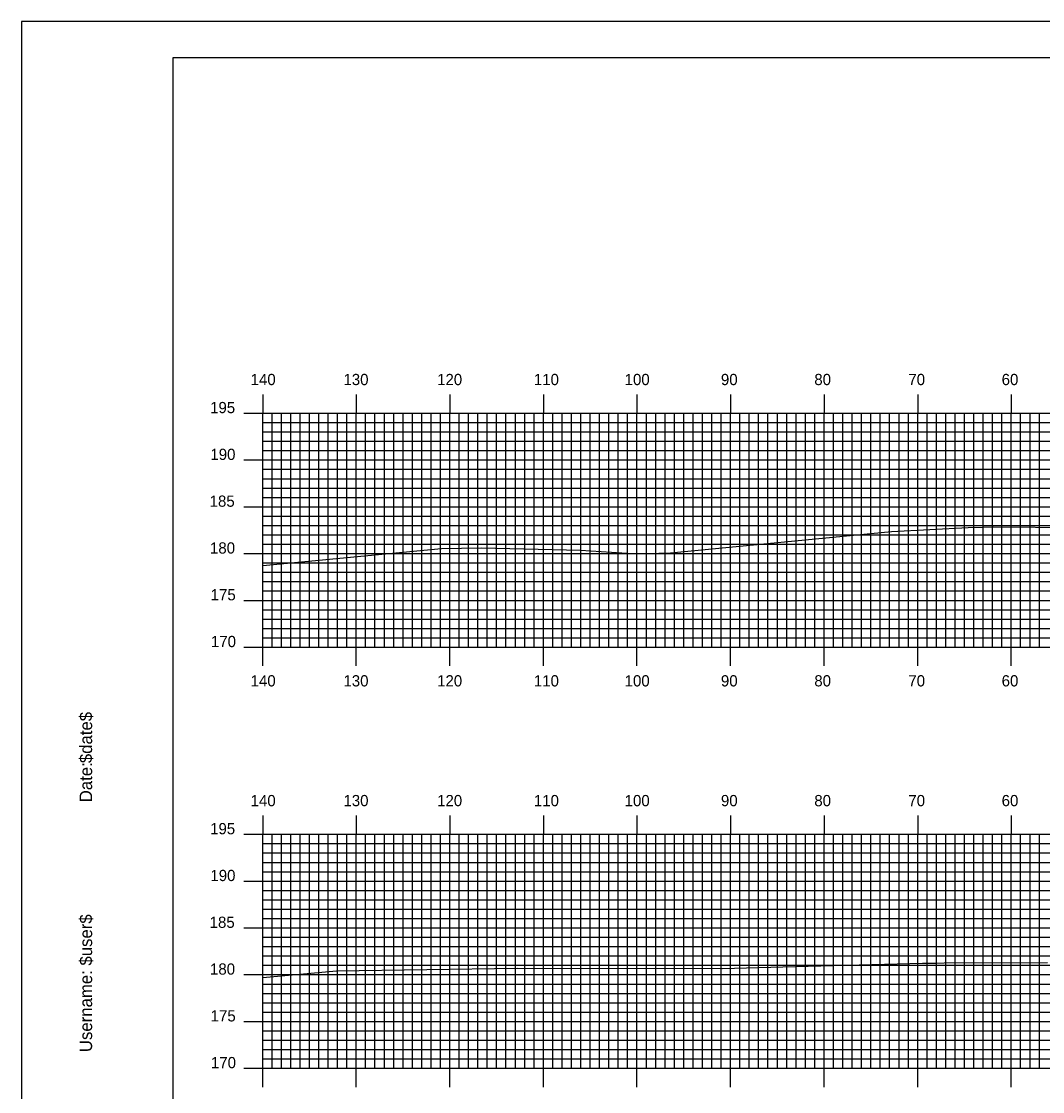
# Model space of a CAD drawing. Extents: x 1823571 to 1823914, y 442310 to 442530.
# Drawn here: x 1823571.1 to 1823680.2, y 442415.6 to 442530 of the extents above; entities that cross this region are included whole.
import ezdxf

# ---------------------------------------------------------------- set-up
doc = ezdxf.new("R2010")
doc.units = 0
for name, color, linetype in [('BORDER', 7, 'Continuous'), ('H_V ANNOTATION', 7, 'Continuous'), ('MAJOR', 7, 'Continuous'), ('MINOR', 7, 'Continuous'), ('PLOT BOUNDARY', 7, 'Continuous'), ('S_Roadway_Centerline', 7, 'Continuous')]:
    doc.layers.add(name, color=color, linetype=linetype)

msp = doc.modelspace()

# ---------------------------------------------------------------- linework, layer by layer
at = {"layer": 'BORDER'}
msp.add_lwpolyline([(1823587.3, 442316.11), (1823907.3, 442316.11), (1823907.3, 442526.11), (1823587.3, 442526.11)], close=True, dxfattribs=at)
at = {"layer": 'MAJOR'}
for p, q in [((1823596.9, 442490.12), (1823596.9, 442488.12)), ((1823606.9, 442490.12), (1823606.9, 442488.12)), ((1823616.9, 442490.12), (1823616.9, 442488.12)), ((1823626.9, 442490.12), (1823626.9, 442488.12)), ((1823636.9, 442490.12), (1823636.9, 442488.12)), ((1823646.9, 442490.12), (1823646.9, 442488.12)), ((1823656.9, 442490.12), (1823656.9, 442488.12)), ((1823666.9, 442490.12), (1823666.9, 442488.12)), ((1823676.9, 442490.12), (1823676.9, 442488.12)), ((1823594.9, 442488.12), (1823596.9, 442488.12)), ((1823596.9, 442488.12), (1823876.9, 442488.12)), ((1823596.9, 442463.12), (1823596.9, 442488.12)), ((1823596.9, 442463.12), (1823596.9, 442488.12)), ((1823596.9, 442488.12), (1823876.9, 442488.12)), ((1823606.9, 442463.12), (1823606.9, 442488.12)), ((1823616.9, 442463.12), (1823616.9, 442488.12)), ((1823626.9, 442463.12), (1823626.9, 442488.12)), ((1823636.9, 442463.12), (1823636.9, 442488.12)), ((1823646.9, 442463.12), (1823646.9, 442488.12)), ((1823656.9, 442463.12), (1823656.9, 442488.12)), ((1823666.9, 442463.12), (1823666.9, 442488.12)), ((1823676.9, 442463.12), (1823676.9, 442488.12)), ((1823594.9, 442483.12), (1823596.9, 442483.12)), ((1823596.9, 442483.12), (1823876.9, 442483.12)), ((1823594.9, 442478.12), (1823596.9, 442478.12)), ((1823596.9, 442478.12), (1823876.9, 442478.12)), ((1823594.9, 442473.12), (1823596.9, 442473.12)), ((1823596.9, 442473.12), (1823876.9, 442473.12)), ((1823594.9, 442468.12), (1823596.9, 442468.12)), ((1823596.9, 442468.12), (1823876.9, 442468.12)), ((1823594.9, 442463.12), (1823596.9, 442463.12)), ((1823596.9, 442463.12), (1823876.9, 442463.12)), ((1823596.9, 442463.12), (1823876.9, 442463.12)), ((1823596.9, 442461.11), (1823596.9, 442463.12)), ((1823606.9, 442461.11), (1823606.9, 442463.12)), ((1823616.9, 442461.11), (1823616.9, 442463.12)), ((1823626.9, 442461.11), (1823626.9, 442463.12)), ((1823636.9, 442461.11), (1823636.9, 442463.12)), ((1823646.9, 442461.11), (1823646.9, 442463.12)), ((1823656.9, 442461.11), (1823656.9, 442463.12)), ((1823666.9, 442461.11), (1823666.9, 442463.12)), ((1823676.9, 442461.11), (1823676.9, 442463.12)), ((1823596.9, 442445.12), (1823596.9, 442443.12)), ((1823606.9, 442445.12), (1823606.9, 442443.12)), ((1823616.9, 442445.12), (1823616.9, 442443.12)), ((1823626.9, 442445.12), (1823626.9, 442443.12)), ((1823636.9, 442445.12), (1823636.9, 442443.12)), ((1823646.9, 442445.12), (1823646.9, 442443.12)), ((1823656.9, 442445.12), (1823656.9, 442443.12)), ((1823666.9, 442445.12), (1823666.9, 442443.12)), ((1823676.9, 442445.12), (1823676.9, 442443.12)), ((1823594.9, 442443.12), (1823596.9, 442443.12)), ((1823596.9, 442443.12), (1823876.9, 442443.12)), ((1823596.9, 442418.12), (1823596.9, 442443.12)), ((1823596.9, 442418.12), (1823596.9, 442443.12)), ((1823596.9, 442443.12), (1823876.9, 442443.12)), ((1823606.9, 442418.12), (1823606.9, 442443.12)), ((1823616.9, 442418.12), (1823616.9, 442443.12)), ((1823626.9, 442418.12), (1823626.9, 442443.12)), ((1823636.9, 442418.12), (1823636.9, 442443.12)), ((1823646.9, 442418.12), (1823646.9, 442443.12)), ((1823656.9, 442418.12), (1823656.9, 442443.12)), ((1823666.9, 442418.12), (1823666.9, 442443.12)), ((1823676.9, 442418.12), (1823676.9, 442443.12)), ((1823594.9, 442438.12), (1823596.9, 442438.12)), ((1823596.9, 442438.12), (1823876.9, 442438.12)), ((1823594.9, 442433.12), (1823596.9, 442433.12)), ((1823596.9, 442433.12), (1823876.9, 442433.12)), ((1823594.9, 442428.12), (1823596.9, 442428.12)), ((1823596.9, 442428.12), (1823876.9, 442428.12)), ((1823594.9, 442423.12), (1823596.9, 442423.12)), ((1823596.9, 442423.12), (1823876.9, 442423.12)), ((1823594.9, 442418.12), (1823596.9, 442418.12)), ((1823596.9, 442418.12), (1823876.9, 442418.12)), ((1823596.9, 442418.12), (1823876.9, 442418.12)), ((1823596.9, 442416.11), (1823596.9, 442418.12)), ((1823606.9, 442416.11), (1823606.9, 442418.12)), ((1823616.9, 442416.11), (1823616.9, 442418.12)), ((1823626.9, 442416.11), (1823626.9, 442418.12)), ((1823636.9, 442416.11), (1823636.9, 442418.12)), ((1823646.9, 442416.11), (1823646.9, 442418.12)), ((1823656.9, 442416.11), (1823656.9, 442418.12)), ((1823666.9, 442416.11), (1823666.9, 442418.12)), ((1823676.9, 442416.11), (1823676.9, 442418.12))]:
    msp.add_line(p, q, dxfattribs=at)
at = {"layer": 'MINOR'}
for p, q in [((1823597.9, 442463.12), (1823597.9, 442488.12)), ((1823598.9, 442463.12), (1823598.9, 442488.12)), ((1823599.9, 442463.12), (1823599.9, 442488.12)), ((1823600.9, 442463.12), (1823600.9, 442488.12)), ((1823601.9, 442463.12), (1823601.9, 442488.12)), ((1823602.9, 442463.12), (1823602.9, 442488.12)), ((1823603.9, 442463.12), (1823603.9, 442488.12)), ((1823604.9, 442463.12), (1823604.9, 442488.12)), ((1823605.9, 442463.12), (1823605.9, 442488.12)), ((1823607.9, 442463.12), (1823607.9, 442488.12)), ((1823608.9, 442463.12), (1823608.9, 442488.12)), ((1823609.9, 442463.12), (1823609.9, 442488.12)), ((1823610.9, 442463.12), (1823610.9, 442488.12)), ((1823611.9, 442463.12), (1823611.9, 442488.12)), ((1823612.9, 442463.12), (1823612.9, 442488.12)), ((1823613.9, 442463.12), (1823613.9, 442488.12)), ((1823614.9, 442463.12), (1823614.9, 442488.12)), ((1823615.9, 442463.12), (1823615.9, 442488.12)), ((1823617.9, 442463.12), (1823617.9, 442488.12)), ((1823618.9, 442463.12), (1823618.9, 442488.12)), ((1823619.9, 442463.12), (1823619.9, 442488.12)), ((1823620.9, 442463.12), (1823620.9, 442488.12)), ((1823621.9, 442463.12), (1823621.9, 442488.12)), ((1823622.9, 442463.12), (1823622.9, 442488.12)), ((1823623.9, 442463.12), (1823623.9, 442488.12)), ((1823624.9, 442463.12), (1823624.9, 442488.12)), ((1823625.9, 442463.12), (1823625.9, 442488.12)), ((1823627.9, 442463.12), (1823627.9, 442488.12)), ((1823628.9, 442463.12), (1823628.9, 442488.12)), ((1823629.9, 442463.12), (1823629.9, 442488.12)), ((1823630.9, 442463.12), (1823630.9, 442488.12)), ((1823631.9, 442463.12), (1823631.9, 442488.12)), ((1823632.9, 442463.12), (1823632.9, 442488.12)), ((1823633.9, 442463.12), (1823633.9, 442488.12)), ((1823634.9, 442463.12), (1823634.9, 442488.12)), ((1823635.9, 442463.12), (1823635.9, 442488.12)), ((1823637.9, 442463.12), (1823637.9, 442488.12)), ((1823638.9, 442463.12), (1823638.9, 442488.12)), ((1823639.9, 442463.12), (1823639.9, 442488.12)), ((1823640.9, 442463.12), (1823640.9, 442488.12)), ((1823641.9, 442463.12), (1823641.9, 442488.12)), ((1823642.9, 442463.12), (1823642.9, 442488.12)), ((1823643.9, 442463.12), (1823643.9, 442488.12)), ((1823644.9, 442463.12), (1823644.9, 442488.12)), ((1823645.9, 442463.12), (1823645.9, 442488.12)), ((1823647.9, 442463.12), (1823647.9, 442488.12)), ((1823648.9, 442463.12), (1823648.9, 442488.12)), ((1823649.9, 442463.12), (1823649.9, 442488.12)), ((1823650.9, 442463.12), (1823650.9, 442488.12)), ((1823651.9, 442463.12), (1823651.9, 442488.12)), ((1823652.9, 442463.12), (1823652.9, 442488.12)), ((1823653.9, 442463.12), (1823653.9, 442488.12)), ((1823654.9, 442463.12), (1823654.9, 442488.12)), ((1823655.9, 442463.12), (1823655.9, 442488.12)), ((1823657.9, 442463.12), (1823657.9, 442488.12)), ((1823658.9, 442463.12), (1823658.9, 442488.12)), ((1823659.9, 442463.12), (1823659.9, 442488.12)), ((1823660.9, 442463.12), (1823660.9, 442488.12)), ((1823661.9, 442463.12), (1823661.9, 442488.12)), ((1823662.9, 442463.12), (1823662.9, 442488.12)), ((1823663.9, 442463.12), (1823663.9, 442488.12)), ((1823664.9, 442463.12), (1823664.9, 442488.12)), ((1823665.9, 442463.12), (1823665.9, 442488.12)), ((1823667.9, 442463.12), (1823667.9, 442488.12)), ((1823668.9, 442463.12), (1823668.9, 442488.12)), ((1823669.9, 442463.12), (1823669.9, 442488.12)), ((1823670.9, 442463.12), (1823670.9, 442488.12)), ((1823671.9, 442463.12), (1823671.9, 442488.12)), ((1823672.9, 442463.12), (1823672.9, 442488.12)), ((1823673.9, 442463.12), (1823673.9, 442488.12)), ((1823674.9, 442463.12), (1823674.9, 442488.12)), ((1823675.9, 442463.12), (1823675.9, 442488.12)), ((1823677.9, 442463.12), (1823677.9, 442488.12)), ((1823678.9, 442463.12), (1823678.9, 442488.12)), ((1823679.9, 442463.12), (1823679.9, 442488.12)), ((1823596.9, 442487.12), (1823876.9, 442487.12)), ((1823596.9, 442487.12), (1823598.9, 442487.12)), ((1823596.9, 442486.12), (1823876.9, 442486.12)), ((1823596.9, 442486.12), (1823598.9, 442486.12)), ((1823596.9, 442485.12), (1823876.9, 442485.12)), ((1823596.9, 442485.12), (1823598.9, 442485.12)), ((1823596.9, 442484.12), (1823876.9, 442484.12)), ((1823596.9, 442484.12), (1823598.9, 442484.12)), ((1823596.9, 442482.12), (1823876.9, 442482.12)), ((1823596.9, 442482.12), (1823598.9, 442482.12)), ((1823596.9, 442481.12), (1823876.9, 442481.12)), ((1823596.9, 442481.12), (1823598.9, 442481.12)), ((1823596.9, 442480.12), (1823876.9, 442480.12)), ((1823596.9, 442480.12), (1823598.9, 442480.12)), ((1823596.9, 442479.12), (1823876.9, 442479.12)), ((1823596.9, 442479.12), (1823598.9, 442479.12)), ((1823596.9, 442477.12), (1823876.9, 442477.12)), ((1823596.9, 442477.12), (1823598.9, 442477.12)), ((1823596.9, 442476.12), (1823876.9, 442476.12)), ((1823596.9, 442476.12), (1823598.9, 442476.12)), ((1823596.9, 442475.12), (1823876.9, 442475.12)), ((1823596.9, 442475.12), (1823598.9, 442475.12)), ((1823596.9, 442474.12), (1823876.9, 442474.12)), ((1823596.9, 442474.12), (1823598.9, 442474.12)), ((1823596.9, 442472.12), (1823876.9, 442472.12)), ((1823596.9, 442472.12), (1823598.9, 442472.12)), ((1823596.9, 442471.12), (1823876.9, 442471.12)), ((1823596.9, 442471.12), (1823598.9, 442471.12)), ((1823596.9, 442470.12), (1823876.9, 442470.12)), ((1823596.9, 442470.12), (1823598.9, 442470.12)), ((1823596.9, 442469.12), (1823876.9, 442469.12)), ((1823596.9, 442469.12), (1823598.9, 442469.12)), ((1823596.9, 442467.12), (1823876.9, 442467.12)), ((1823596.9, 442467.12), (1823598.9, 442467.12)), ((1823596.9, 442466.12), (1823876.9, 442466.12)), ((1823596.9, 442466.12), (1823598.9, 442466.12)), ((1823596.9, 442465.12), (1823876.9, 442465.12)), ((1823596.9, 442465.12), (1823598.9, 442465.12)), ((1823596.9, 442464.12), (1823876.9, 442464.12)), ((1823596.9, 442464.12), (1823598.9, 442464.12)), ((1823597.9, 442418.12), (1823597.9, 442443.12)), ((1823598.9, 442418.12), (1823598.9, 442443.12)), ((1823599.9, 442418.12), (1823599.9, 442443.12)), ((1823600.9, 442418.12), (1823600.9, 442443.12)), ((1823601.9, 442418.12), (1823601.9, 442443.12)), ((1823602.9, 442418.12), (1823602.9, 442443.12)), ((1823603.9, 442418.12), (1823603.9, 442443.12)), ((1823604.9, 442418.12), (1823604.9, 442443.12)), ((1823605.9, 442418.12), (1823605.9, 442443.12)), ((1823607.9, 442418.12), (1823607.9, 442443.12)), ((1823608.9, 442418.12), (1823608.9, 442443.12)), ((1823609.9, 442418.12), (1823609.9, 442443.12)), ((1823610.9, 442418.12), (1823610.9, 442443.12)), ((1823611.9, 442418.12), (1823611.9, 442443.12)), ((1823612.9, 442418.12), (1823612.9, 442443.12)), ((1823613.9, 442418.12), (1823613.9, 442443.12)), ((1823614.9, 442418.12), (1823614.9, 442443.12)), ((1823615.9, 442418.12), (1823615.9, 442443.12)), ((1823617.9, 442418.12), (1823617.9, 442443.12)), ((1823618.9, 442418.12), (1823618.9, 442443.12)), ((1823619.9, 442418.12), (1823619.9, 442443.12)), ((1823620.9, 442418.12), (1823620.9, 442443.12)), ((1823621.9, 442418.12), (1823621.9, 442443.12)), ((1823622.9, 442418.12), (1823622.9, 442443.12)), ((1823623.9, 442418.12), (1823623.9, 442443.12)), ((1823624.9, 442418.12), (1823624.9, 442443.12)), ((1823625.9, 442418.12), (1823625.9, 442443.12)), ((1823627.9, 442418.12), (1823627.9, 442443.12)), ((1823628.9, 442418.12), (1823628.9, 442443.12)), ((1823629.9, 442418.12), (1823629.9, 442443.12)), ((1823630.9, 442418.12), (1823630.9, 442443.12)), ((1823631.9, 442418.12), (1823631.9, 442443.12)), ((1823632.9, 442418.12), (1823632.9, 442443.12)), ((1823633.9, 442418.12), (1823633.9, 442443.12)), ((1823634.9, 442418.12), (1823634.9, 442443.12)), ((1823635.9, 442418.12), (1823635.9, 442443.12)), ((1823637.9, 442418.12), (1823637.9, 442443.12)), ((1823638.9, 442418.12), (1823638.9, 442443.12)), ((1823639.9, 442418.12), (1823639.9, 442443.12)), ((1823640.9, 442418.12), (1823640.9, 442443.12)), ((1823641.9, 442418.12), (1823641.9, 442443.12)), ((1823642.9, 442418.12), (1823642.9, 442443.12)), ((1823643.9, 442418.12), (1823643.9, 442443.12)), ((1823644.9, 442418.12), (1823644.9, 442443.12)), ((1823645.9, 442418.12), (1823645.9, 442443.12)), ((1823647.9, 442418.12), (1823647.9, 442443.12)), ((1823648.9, 442418.12), (1823648.9, 442443.12)), ((1823649.9, 442418.12), (1823649.9, 442443.12)), ((1823650.9, 442418.12), (1823650.9, 442443.12)), ((1823651.9, 442418.12), (1823651.9, 442443.12)), ((1823652.9, 442418.12), (1823652.9, 442443.12)), ((1823653.9, 442418.12), (1823653.9, 442443.12)), ((1823654.9, 442418.12), (1823654.9, 442443.12)), ((1823655.9, 442418.12), (1823655.9, 442443.12)), ((1823657.9, 442418.12), (1823657.9, 442443.12)), ((1823658.9, 442418.12), (1823658.9, 442443.12)), ((1823659.9, 442418.12), (1823659.9, 442443.12)), ((1823660.9, 442418.12), (1823660.9, 442443.12)), ((1823661.9, 442418.12), (1823661.9, 442443.12)), ((1823662.9, 442418.12), (1823662.9, 442443.12)), ((1823663.9, 442418.12), (1823663.9, 442443.12)), ((1823664.9, 442418.12), (1823664.9, 442443.12)), ((1823665.9, 442418.12), (1823665.9, 442443.12)), ((1823667.9, 442418.12), (1823667.9, 442443.12)), ((1823668.9, 442418.12), (1823668.9, 442443.12)), ((1823669.9, 442418.12), (1823669.9, 442443.12)), ((1823670.9, 442418.12), (1823670.9, 442443.12)), ((1823671.9, 442418.12), (1823671.9, 442443.12)), ((1823672.9, 442418.12), (1823672.9, 442443.12)), ((1823673.9, 442418.12), (1823673.9, 442443.12)), ((1823674.9, 442418.12), (1823674.9, 442443.12)), ((1823675.9, 442418.12), (1823675.9, 442443.12)), ((1823677.9, 442418.12), (1823677.9, 442443.12)), ((1823678.9, 442418.12), (1823678.9, 442443.12)), ((1823679.9, 442418.12), (1823679.9, 442443.12)), ((1823596.9, 442442.12), (1823876.9, 442442.12)), ((1823596.9, 442442.12), (1823598.9, 442442.12)), ((1823596.9, 442441.12), (1823876.9, 442441.12)), ((1823596.9, 442441.12), (1823598.9, 442441.12)), ((1823596.9, 442440.12), (1823876.9, 442440.12)), ((1823596.9, 442440.12), (1823598.9, 442440.12)), ((1823596.9, 442439.12), (1823876.9, 442439.12)), ((1823596.9, 442439.12), (1823598.9, 442439.12)), ((1823596.9, 442437.12), (1823876.9, 442437.12)), ((1823596.9, 442437.12), (1823598.9, 442437.12)), ((1823596.9, 442436.12), (1823876.9, 442436.12)), ((1823596.9, 442436.12), (1823598.9, 442436.12)), ((1823596.9, 442435.12), (1823876.9, 442435.12)), ((1823596.9, 442435.12), (1823598.9, 442435.12)), ((1823596.9, 442434.12), (1823876.9, 442434.12)), ((1823596.9, 442434.12), (1823598.9, 442434.12)), ((1823596.9, 442432.12), (1823876.9, 442432.12)), ((1823596.9, 442432.12), (1823598.9, 442432.12)), ((1823596.9, 442431.12), (1823876.9, 442431.12)), ((1823596.9, 442431.12), (1823598.9, 442431.12)), ((1823596.9, 442430.12), (1823876.9, 442430.12)), ((1823596.9, 442430.12), (1823598.9, 442430.12)), ((1823596.9, 442429.12), (1823876.9, 442429.12)), ((1823596.9, 442429.12), (1823598.9, 442429.12)), ((1823596.9, 442427.12), (1823876.9, 442427.12)), ((1823596.9, 442427.12), (1823598.9, 442427.12)), ((1823596.9, 442426.12), (1823876.9, 442426.12)), ((1823596.9, 442426.12), (1823598.9, 442426.12)), ((1823596.9, 442425.12), (1823876.9, 442425.12)), ((1823596.9, 442425.12), (1823598.9, 442425.12)), ((1823596.9, 442424.12), (1823876.9, 442424.12)), ((1823596.9, 442424.12), (1823598.9, 442424.12)), ((1823596.9, 442422.12), (1823876.9, 442422.12)), ((1823596.9, 442422.12), (1823598.9, 442422.12)), ((1823596.9, 442421.12), (1823876.9, 442421.12)), ((1823596.9, 442421.12), (1823598.9, 442421.12)), ((1823596.9, 442420.12), (1823876.9, 442420.12)), ((1823596.9, 442420.12), (1823598.9, 442420.12)), ((1823596.9, 442419.12), (1823876.9, 442419.12)), ((1823596.9, 442419.12), (1823598.9, 442419.12))]:
    msp.add_line(p, q, dxfattribs=at)
at = {"layer": 'PLOT BOUNDARY'}
msp.add_lwpolyline([(1823571.11, 442309.99), (1823911.11, 442309.99), (1823911.11, 442529.99), (1823571.11, 442529.99)], close=True, dxfattribs=at)
at = {"layer": 'S_Roadway_Centerline'}
for points in [[(1823596.9, 442471.84), (1823616.02, 442473.67), (1823620.28, 442473.73), (1823630.87, 442473.49), (1823636.39, 442473.14), (1823637.98, 442473.14), (1823640.47, 442473.2), (1823664.11, 442475.48), (1823672.28, 442475.9), (1823673.94, 442475.95), (1823675.04, 442475.99), (1823683.92, 442475.89)], [(1823596.9, 442427.81), (1823604.79, 442428.54), (1823624.11, 442428.8), (1823646.05, 442428.79), (1823652.47, 442428.95), (1823667.4, 442429.33), (1823668.51, 442429.35), (1823668.93, 442429.36), (1823669.73, 442429.37), (1823680.77, 442429.42)]]:
    msp.add_lwpolyline(points, dxfattribs=at)

# ---------------------------------------------------------------- texts
at = {"layer": 'BORDER'}
for s, p in [('$date$', (1823578.67, 442450.72)), ('Date:', (1823578.67, 442446.54)), ('$user$', (1823578.67, 442429.09)), ('Username:', (1823578.67, 442419.84))]:
    msp.add_text(s, height=1.339, rotation=90, dxfattribs=at).set_placement(p)
at = {"layer": 'H_V ANNOTATION'}
for s, p in [('140', (1823595.61, 442491.12)), ('130', (1823605.53, 442491.12)), ('120', (1823615.54, 442491.12)), ('110', (1823625.88, 442491.12)), ('100', (1823635.58, 442491.12)), ('90', (1823645.87, 442491.12)), ('80', (1823655.85, 442491.12)), ('70', (1823665.9, 442491.12)), ('60', (1823675.87, 442491.12)), ('195', (1823591.28, 442488.12)), ('190', (1823591.31, 442483.12)), ('185', (1823591.23, 442478.12)), ('180', (1823591.27, 442473.12)), ('175', (1823591.34, 442468.12)), ('170', (1823591.37, 442463.12)), ('140', (1823595.61, 442458.92)), ('130', (1823605.53, 442458.92)), ('120', (1823615.54, 442458.92)), ('110', (1823625.88, 442458.92)), ('100', (1823635.58, 442458.92)), ('90', (1823645.87, 442458.92)), ('80', (1823655.85, 442458.92)), ('70', (1823665.9, 442458.92)), ('60', (1823675.87, 442458.92)), ('140', (1823595.61, 442446.12)), ('130', (1823605.53, 442446.12)), ('120', (1823615.54, 442446.12)), ('110', (1823625.88, 442446.12)), ('100', (1823635.58, 442446.12)), ('90', (1823645.87, 442446.12)), ('80', (1823655.85, 442446.12)), ('70', (1823665.9, 442446.12)), ('60', (1823675.87, 442446.12)), ('195', (1823591.28, 442443.12)), ('190', (1823591.31, 442438.12)), ('185', (1823591.23, 442433.12)), ('180', (1823591.27, 442428.12)), ('175', (1823591.34, 442423.12)), ('170', (1823591.37, 442418.12))]:
    msp.add_text(s, height=1.2, dxfattribs=at).set_placement(p)
at = {"layer": 'MAJOR'}
for p in [(1823596.89, 442485.68), (1823596.89, 442463.12), (1823596.89, 442418.12)]:
    msp.add_text('-', height=0.012, dxfattribs=at).set_placement(p)

doc.saveas('drawing.dxf')
